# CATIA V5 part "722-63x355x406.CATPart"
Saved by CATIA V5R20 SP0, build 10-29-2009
Part number: 722-63x355x406
Definition: NONE
Nomenclature: 722-63x355x406
Source: Unknown
Description: 722-63x355x406
Bounding box of the stored display mesh (mm): x -31.5 to 31.5, y -31.5 to 31.5, z -337 to 69
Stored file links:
  C:\Users\Utente\Desktop\IO LAVORO\3D X SITO CF\X SITO\722\722-63x355x406.CATPart
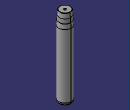
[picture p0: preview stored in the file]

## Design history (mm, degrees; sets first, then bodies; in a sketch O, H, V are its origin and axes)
Body1 "722-63x355x406" (main body)
  Solid1: solid without history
